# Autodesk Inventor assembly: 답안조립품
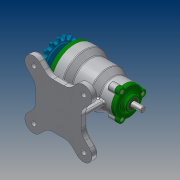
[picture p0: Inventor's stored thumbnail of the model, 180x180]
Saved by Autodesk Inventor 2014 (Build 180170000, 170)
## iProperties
Created: 2017-03
Part Number: 답안조립품
Document SubType Name: Assembly
Designer: Administrator
Author: Administrator
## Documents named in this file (14)
- C:\Users\Administrator.WIN7-20150702GK\Desktop\470308V1012\답안조립품.iam
- C:\Users\Administrator.WIN7-20150702GK\Desktop\470308V1012\본체.ipt
- C:\Users\Administrator.WIN7-20150702GK\Desktop\470308V1012\뒤커버.ipt
- C:\Users\Administrator.WIN7-20150702GK\Desktop\470308V1012\베어링-6200.ipt
- C:\Users\Administrator.WIN7-20150702GK\Desktop\470308V1012\베어링-6203.ipt
- C:\Users\Administrator.WIN7-20150702GK\Desktop\470308V1012\볼트 M4 x 12.ipt
- C:\Users\Administrator.WIN7-20150702GK\Desktop\470308V1012\볼트 M5 x 10.ipt
- 볼트 M5 x 10.ipt
- C:\Users\Administrator.WIN7-20150702GK\Desktop\470308V1012\스프로킷.ipt
- C:\Users\Administrator.WIN7-20150702GK\Desktop\470308V1012\앞커버.ipt
- C:\Users\Administrator.WIN7-20150702GK\Desktop\470308V1012\오일 실 10 20 7.ipt
- C:\Users\Administrator.WIN7-20150702GK\Desktop\470308V1012\오일 실 17 30 8.ipt
- C:\Users\Administrator.WIN7-20150702GK\Desktop\470308V1012\축.ipt
- C:\Users\Administrator.WIN7-20150702GK\Desktop\470308V1012\키5x5.ipt
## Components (9 placed, 1 different names)
1. ISO 4762 M4 x 12:1 — 각도:1
2. ISO 4762 M4 x 12:2 — 각도:4
3. ISO 4762 M4 x 12:3 — 각도:10
4. ISO 4762 M4 x 12:4 — 각도:8
5. ISO 4762 M4 x 12:5 — 각도:7
6. ISO 4762 M4 x 12:6 — 각도:11
7. ISO 4762 M4 x 12:7 — 각도:9
8. ISO 4762 M4 x 12:8 — 각도:5
9. ISO 4762 M4 x 12:9 — 각도:6
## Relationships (9: Angle 9)
- 각도:1 [Angle]: ISO 4762 M4 x 12:1
- 각도:4 [Angle]: ISO 4762 M4 x 12:2
- 각도:5 [Angle]: ISO 4762 M4 x 12:8
- 각도:6 [Angle]: ISO 4762 M4 x 12:9
- 각도:7 [Angle]: ISO 4762 M4 x 12:5
- 각도:8 [Angle]: ISO 4762 M4 x 12:4
- 각도:9 [Angle]: ISO 4762 M4 x 12:7
- 각도:10 [Angle]: ISO 4762 M4 x 12:3
- 각도:11 [Angle]: ISO 4762 M4 x 12:6
